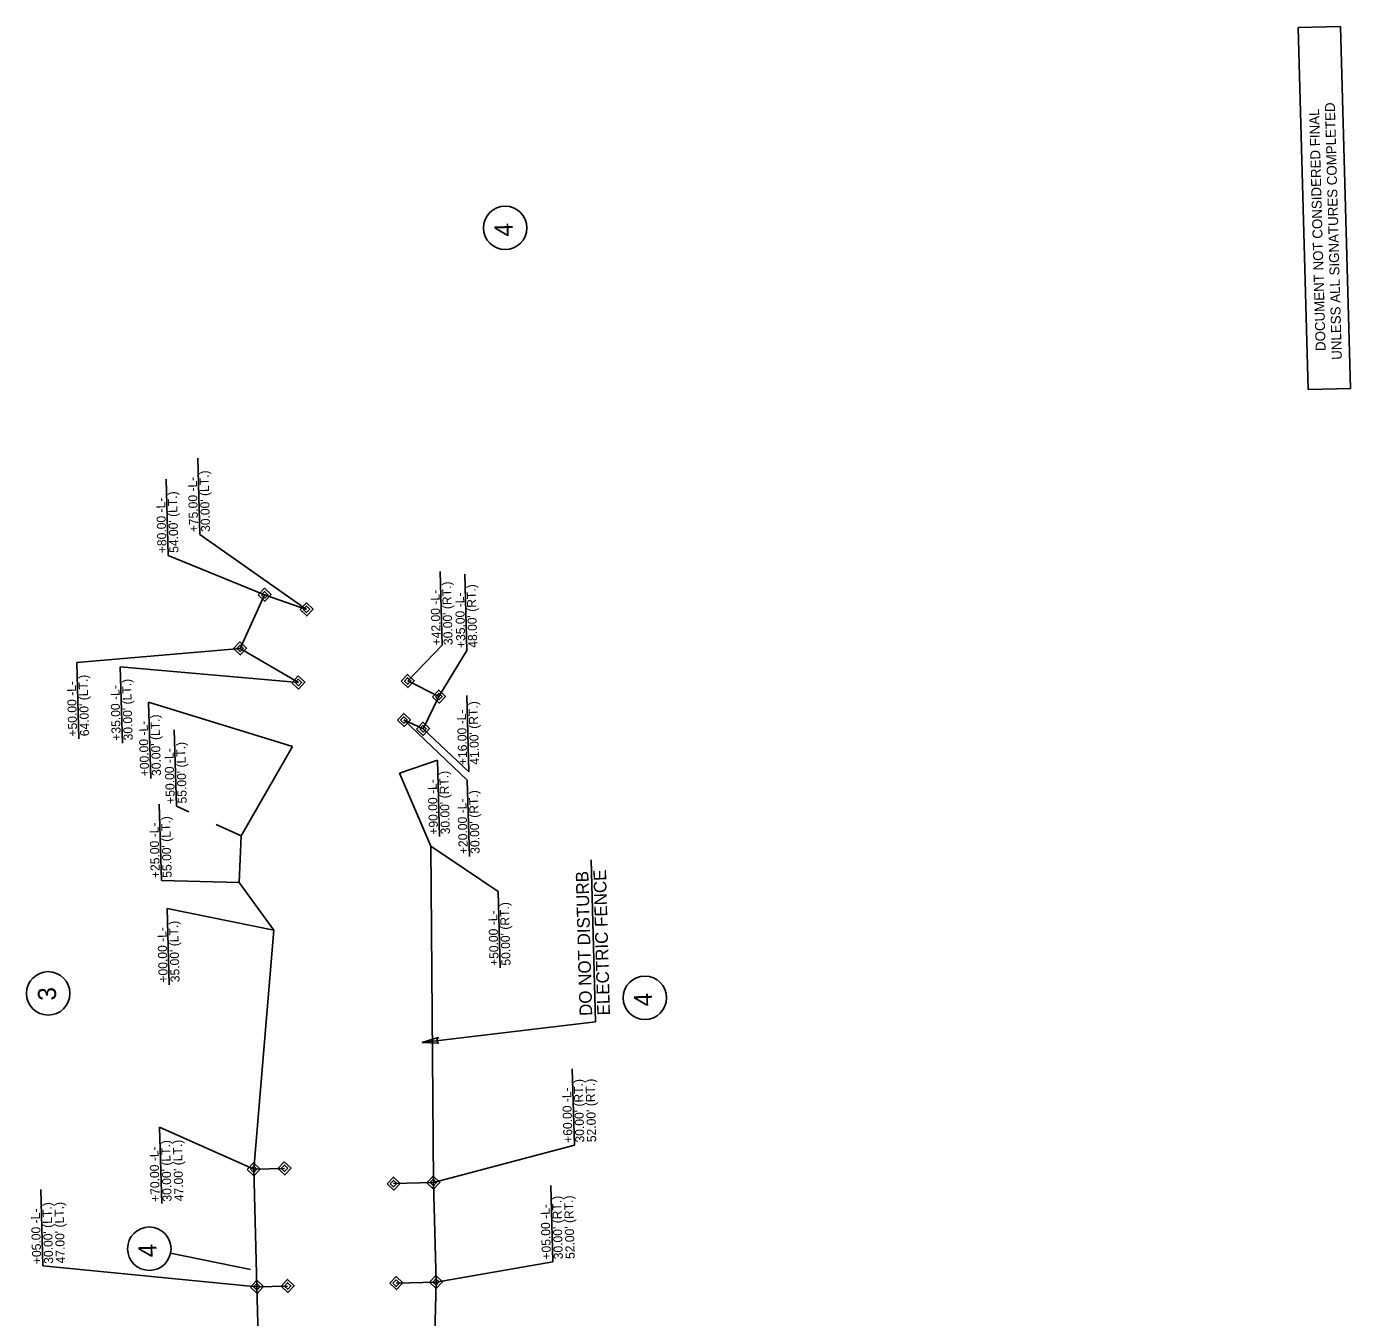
# Model space of a CAD drawing. Extents: x 1835710 to 1836442, y 994022 to 995358.
# Drawn here: x 1835710 to 1836442, y 994644 to 995358 of the extents above; entities that cross this region are included whole.
import ezdxf

# ---------------------------------------------------------------- set-up
doc = ezdxf.new("R2010")
doc.units = 0
for name, color, linetype in [('Prop Dimension', 7, 'Continuous'), ('Prop Dimension Text', 7, 'Continuous'), ('Prop Easement Construction', 7, 'Continuous'), ('Prop Easement Construction Station Offsets', 7, 'Continuous'), ('Prop Easement Permanent Drainage', 7, 'Continuous'), ('Prop Easement Permanent Drainage Station Offsets', 7, 'Continuous'), ('Prop Parcel Number CELL', 7, 'Continuous'), ('Prop ROW Marker CELL', 7, 'Continuous'), ('Prop ROW Permanent Easement CELL', 7, 'Continuous'), ('Prop ROW Station Offsets', 7, 'Continuous'), ('Prop ROW Text', 7, 'Continuous'), ('Prop Terminator CELL', 7, 'Continuous'), ('Sheet Sticker Exception Certification CELL', 7, 'Continuous')]:
    doc.layers.add(name, color=color, linetype=linetype)

msp = doc.modelspace()

# ---------------------------------------------------------------- linework, layer by layer
at = {"layer": 'Prop Dimension'}
for p in [(1836022.11, 994897.14), (1835928.86, 994796.23)]:
    msp.add_line(p, (1836024.55, 994807.69), dxfattribs=at)
at = {"layer": 'Prop Easement Construction'}
for p, q in [((1835828.79, 994910.29), (1835857.17, 994959.67)), ((1835933.64, 994904.69), (1835916.21, 994945.01)), ((1835827.6, 994884.56), (1835828.79, 994910.29)), ((1835934.97, 994718.82), (1835933.64, 994904.69)), ((1835846.75, 994858.3), (1835827.6, 994884.56)), ((1835835.74, 994726.16), (1835846.75, 994858.3)), ((1835933.19, 994523.7), (1835936.44, 994663.83)), ((1835841.09, 994526.23), (1835837.48, 994661.18))]:
    msp.add_line(p, q, dxfattribs=at)
at = {"layer": 'Prop Easement Construction Station Offsets'}
for p, q in [((1835778.8, 994941.99), (1835777.64, 994984.2)), ((1835777.64, 994984.2), (1835857.17, 994959.67)), ((1835793.01, 994926.79), (1835791.86, 994968.99)), ((1835937.25, 994952.15), (1835916.21, 994945.01)), ((1835938.4, 994909.95), (1835937.25, 994952.15)), ((1835784.72, 994885.75), (1835783.57, 994927.95)), ((1835793.01, 994926.79), (1835799.9, 994923.61)), ((1835814.99, 994916.65), (1835828.79, 994910.29)), ((1835970.74, 994879.6), (1835933.64, 994904.69)), ((1835784.72, 994885.75), (1835827.6, 994884.56)), ((1835971.9, 994837.39), (1835970.74, 994879.6)), ((1835789.1, 994828.01), (1835787.95, 994870.21)), ((1835787.95, 994870.21), (1835846.75, 994858.3))]:
    msp.add_line(p, q, dxfattribs=at)
at = {"layer": 'Prop Easement Permanent Drainage'}
for p, q in [((1835828.18, 995013.95), (1835841.73, 995043.55)), ((1835841.73, 995043.55), (1835864.91, 995035.51)), ((1835860.39, 994995.1), (1835828.18, 995013.95)), ((1835920.79, 994995.94), (1835938, 994987.29)), ((1835929.27, 994969.5), (1835938, 994987.29)), ((1835918.67, 994974.41), (1835929.27, 994969.5)), ((1835852.73, 994726.62), (1835835.74, 994726.16)), ((1835837.48, 994661.18), (1835835.74, 994726.16)), ((1835934.97, 994718.82), (1835912.98, 994718.23)), ((1835936.44, 994663.83), (1835934.97, 994718.82)), ((1835936.44, 994663.83), (1835914.45, 994663.25)), ((1835854.47, 994661.64), (1835837.48, 994661.18))]:
    msp.add_line(p, q, dxfattribs=at)
at = {"layer": 'Prop Easement Permanent Drainage Station Offsets'}
for p, q in [((1835805.91, 995076.83), (1835804.76, 995119.03)), ((1835788.44, 995065.26), (1835787.29, 995107.47)), ((1835805.91, 995076.83), (1835864.91, 995035.51)), ((1835788.44, 995065.26), (1835841.73, 995043.55)), ((1835939.91, 995015.72), (1835938.79, 995056.52)), ((1835953.54, 995012.84), (1835952.39, 995055.04)), ((1835939.91, 995015.72), (1835920.79, 994995.94)), ((1835737.96, 995006.14), (1835828.18, 995013.95)), ((1835953.54, 995012.84), (1835938, 994987.29)), ((1835739.12, 994963.94), (1835737.96, 995006.14)), ((1835763.15, 994961.64), (1835761.99, 995003.85)), ((1835761.99, 995003.85), (1835860.39, 994995.1)), ((1835954.64, 994945.75), (1835953.49, 994987.95)), ((1835953.68, 994941.21), (1835918.67, 994974.41)), ((1835954.64, 994945.75), (1835929.27, 994969.5)), ((1835954.84, 994899.01), (1835953.68, 994941.21)), ((1836012.87, 994739.44), (1836011.72, 994781.64)), ((1835784.9, 994707.28), (1835783.74, 994749.48)), ((1835783.74, 994749.48), (1835835.74, 994726.16)), ((1836012.87, 994739.44), (1835934.97, 994718.82)), ((1836000.98, 994674.91), (1835999.82, 994717.12)), ((1835719.29, 994672.75), (1835718.14, 994714.95)), ((1835719.29, 994672.75), (1835837.48, 994661.18)), ((1836000.98, 994674.91), (1835936.44, 994663.83))]:
    msp.add_line(p, q, dxfattribs=at)
at = {"layer": 'Prop Parcel Number CELL'}
for p, q in [((1835974.62, 995246.27), (1835974.62, 995246.27)), ((1835722.18, 994823.34), (1835722.18, 994823.34)), ((1836051.82, 994820.9), (1836051.82, 994820.9)), ((1835778.04, 994682.25), (1835778.04, 994682.25))]:
    msp.add_line(p, q, dxfattribs=at)
for centre in [(1835974.62, 995246.27), (1835722.18, 994823.34), (1836051.82, 994820.9), (1835778.04, 994682.25)]:
    msp.add_circle(centre, 12, dxfattribs=at)
at = {"layer": 'Prop ROW Marker CELL'}
for p, q in [((1835841.73, 995043.55), (1835841.73, 995043.55)), ((1835864.91, 995035.51), (1835864.91, 995035.51)), ((1835828.18, 995013.95), (1835828.18, 995013.95)), ((1835860.39, 994995.1), (1835860.39, 994995.1)), ((1835920.79, 994995.94), (1835920.79, 994995.94)), ((1835938, 994987.29), (1835938, 994987.29)), ((1835918.67, 994974.41), (1835918.67, 994974.41)), ((1835929.27, 994969.5), (1835929.27, 994969.5)), ((1835835.74, 994726.16), (1835835.74, 994726.16)), ((1835852.73, 994726.62), (1835852.73, 994726.62)), ((1835912.98, 994718.23), (1835912.98, 994718.23)), ((1835934.97, 994718.82), (1835934.97, 994718.82)), ((1835936.44, 994663.83), (1835936.44, 994663.83)), ((1835837.48, 994661.18), (1835837.48, 994661.18)), ((1835854.47, 994661.64), (1835854.47, 994661.64)), ((1835914.45, 994663.25), (1835914.45, 994663.25))]:
    msp.add_line(p, q, dxfattribs=at)
at = {"layer": 'Prop ROW Permanent Easement CELL'}
for points in [[(1835838.13, 995043.46), (1835841.63, 995047.15), (1835845.33, 995043.65), (1835841.83, 995039.96)], [(1835839.93, 995043.5), (1835841.68, 995045.35), (1835843.53, 995043.6), (1835841.78, 995041.75)], [(1835861.32, 995035.41), (1835864.82, 995039.11), (1835868.51, 995035.61), (1835865.01, 995031.91)], [(1835863.11, 995035.46), (1835864.86, 995037.31), (1835866.71, 995035.56), (1835864.96, 995033.71)], [(1835824.59, 995013.86), (1835828.09, 995017.55), (1835831.78, 995014.05), (1835828.28, 995010.36)], [(1835826.38, 995013.91), (1835828.14, 995015.75), (1835829.98, 995014), (1835828.23, 995012.15)], [(1835856.79, 994995), (1835860.3, 994998.7), (1835863.99, 994995.2), (1835860.49, 994991.5)], [(1835858.59, 994995.05), (1835860.34, 994996.9), (1835862.19, 994995.15), (1835860.44, 994993.3)], [(1835917.2, 994995.84), (1835920.7, 994999.54), (1835924.39, 994996.04), (1835920.89, 994992.34)], [(1835919, 994995.89), (1835920.75, 994997.74), (1835922.59, 994995.99), (1835920.84, 994994.14)], [(1835934.4, 994987.19), (1835937.9, 994990.89), (1835941.6, 994987.39), (1835938.1, 994983.69)], [(1835936.2, 994987.24), (1835937.95, 994989.09), (1835939.8, 994987.34), (1835938.05, 994985.49)], [(1835915.08, 994974.31), (1835918.58, 994978.01), (1835922.27, 994974.51), (1835918.77, 994970.81)], [(1835916.88, 994974.36), (1835918.63, 994976.21), (1835920.47, 994974.46), (1835918.72, 994972.61)], [(1835925.67, 994969.41), (1835929.17, 994973.1), (1835932.87, 994969.6), (1835929.37, 994965.9)], [(1835927.47, 994969.45), (1835929.22, 994971.3), (1835931.07, 994969.55), (1835929.32, 994967.7)], [(1835832.14, 994726.06), (1835835.64, 994729.76), (1835839.33, 994726.26), (1835835.83, 994722.56)], [(1835849.13, 994726.52), (1835852.63, 994730.22), (1835856.33, 994726.72), (1835852.83, 994723.02)], [(1835833.94, 994726.11), (1835835.69, 994727.96), (1835837.53, 994726.21), (1835835.78, 994724.36)], [(1835850.93, 994726.57), (1835852.68, 994728.42), (1835854.53, 994726.67), (1835852.78, 994724.82)], [(1835931.37, 994718.72), (1835934.87, 994722.41), (1835938.57, 994718.91), (1835935.07, 994715.22)], [(1835909.38, 994718.13), (1835912.88, 994721.83), (1835916.57, 994718.32), (1835913.07, 994714.63)], [(1835911.18, 994718.18), (1835912.93, 994720.03), (1835914.77, 994718.28), (1835913.02, 994716.43)], [(1835933.17, 994718.77), (1835934.92, 994720.61), (1835936.77, 994718.86), (1835935.02, 994717.02)], [(1835833.88, 994661.09), (1835837.38, 994664.78), (1835841.07, 994661.28), (1835837.57, 994657.59)], [(1835850.87, 994661.54), (1835854.37, 994665.24), (1835858.07, 994661.74), (1835854.57, 994658.04)], [(1835910.85, 994663.15), (1835914.35, 994666.84), (1835918.05, 994663.34), (1835914.55, 994659.65)], [(1835912.65, 994663.2), (1835914.4, 994665.05), (1835916.25, 994663.3), (1835914.5, 994661.45)], [(1835932.84, 994663.74), (1835936.34, 994667.43), (1835940.04, 994663.93), (1835936.54, 994660.24)], [(1835934.64, 994663.79), (1835936.39, 994665.63), (1835938.24, 994663.88), (1835936.49, 994662.04)], [(1835835.68, 994661.14), (1835837.43, 994662.98), (1835839.27, 994661.23), (1835837.52, 994659.39)], [(1835852.67, 994661.59), (1835854.42, 994663.44), (1835856.27, 994661.69), (1835854.52, 994659.84)]]:
    msp.add_lwpolyline(points, close=True, dxfattribs=at)
at = {"layer": 'Prop ROW Station Offsets'}
msp.add_line((1835789.8, 994679.84), (1835833.92, 994670.77), dxfattribs=at)
at = {"layer": 'Prop Terminator CELL'}
msp.add_lwpolyline([(1835937.98, 994795.77), (1835928.86, 994796.23), (1835937.65, 994798.9), (1835936.7, 994797.17)], close=True, dxfattribs=at)
at = {"layer": 'Sheet Sticker Exception Certification CELL'}
for p, q in [((1836418.15, 995156.98), (1836412.69, 995356.94)), ((1836412.7, 995356.94), (1836436.19, 995357.58)), ((1836436.18, 995357.58), (1836441.64, 995157.62)), ((1836441.64, 995157.62), (1836418.15, 995156.98))]:
    msp.add_line(p, q, dxfattribs=at)

# ---------------------------------------------------------------- texts
at = {"layer": 'Prop Dimension Text'}
for s, p in [('ELECTRIC FENCE', (1836032.54, 994811.24)), ('DO NOT DISTURB', (1836022.75, 994810.97))]:
    msp.add_text(s, height=7, rotation=91.56434, dxfattribs=at).set_placement(p)
at = {"layer": 'Prop Easement Construction Station Offsets'}
for s, p in [('+00.00 -L-', (1835777.96, 994943.35)), ("30.00' (LT.)", (1835784.51, 994943.53)), ('+50.00 -L-', (1835792.18, 994928.15)), ("55.00' (LT.)", (1835798.73, 994928.33)), ("30.00' (RT.)", (1835944.14, 994911.27)), ('+90.00 -L-', (1835937.59, 994911.09)), ("55.00' (LT.)", (1835790.44, 994887.29)), ('+25.00 -L-', (1835783.88, 994887.11)), ('+50.00 -L-', (1835971.08, 994838.54)), ("50.00' (RT.)", (1835977.63, 994838.72)), ("35.00' (LT.)", (1835794.82, 994829.55)), ('+00.00 -L-', (1835788.26, 994829.37))]:
    msp.add_text(s, height=5, rotation=91.56434, dxfattribs=at).set_placement(p)
at = {"layer": 'Prop Easement Permanent Drainage Station Offsets'}
for s, p in [("30.00' (LT.)", (1835811.63, 995078.37)), ('+75.00 -L-', (1835805.08, 995078.19)), ('+80.00 -L-', (1835787.6, 995066.62)), ("54.00' (LT.)", (1835794.16, 995066.8)), ('+42.00 -L-', (1835939.11, 995015.68)), ("30.00' (RT.)", (1835945.66, 995015.86)), ('+35.00 -L-', (1835952.71, 995014.2)), ("48.00' (RT.)", (1835959.26, 995014.37)), ('+50.00 -L-', (1835738.28, 994965.3)), ("64.00' (LT.)", (1835744.83, 994965.48)), ('+35.00 -L-', (1835762.31, 994963)), ("30.00' (LT.)", (1835768.86, 994963.18)), ('+16.00 -L-', (1835953.74, 994949.55)), ("41.00' (RT.)", (1835960.29, 994949.73)), ("30.00' (RT.)", (1835960.55, 994900.55)), ('+20.00 -L-', (1835954, 994900.37)), ("30.00' (RT.)", (1836018.4, 994740.99)), ("52.00' (RT.)", (1836024.95, 994741.17)), ('+60.00 -L-', (1836011.85, 994740.81)), ('+70.00 -L-', (1835783.85, 994708.17)), ("30.00' (LT.)", (1835790.4, 994708.35)), ("47.00' (LT.)", (1835796.95, 994708.53)), ("47.00' (LT.)", (1835731.49, 994674.16)), ("30.00' (RT.)", (1836006.51, 994676.47)), ("52.00' (RT.)", (1836013.06, 994676.65)), ('+05.00 -L-', (1835718.38, 994673.8)), ("30.00' (LT.)", (1835724.93, 994673.98)), ('+05.00 -L-', (1835999.96, 994676.29))]:
    msp.add_text(s, height=5, rotation=91.56434, dxfattribs=at).set_placement(p)
at = {"layer": 'Prop ROW Text'}
for s, p in [('4', (1835978.87, 995241.62)), ('3', (1835726.61, 994819.46)), ('4', (1836055.92, 994816.25)), ('4', (1835782.15, 994677.61))]:
    msp.add_text(s, height=10, rotation=91.56434, dxfattribs=at).set_placement(p)
at = {"layer": 'Sheet Sticker Exception Certification CELL'}
for s, p in [('UNLESS ALL SIGNATURES COMPLETED', (1836436.85, 995173.5)), ('DOCUMENT NOT CONSIDERED FINAL', (1836427.91, 995178.33))]:
    msp.add_text(s, height=5.5, rotation=91.56434, dxfattribs=at).set_placement(p)

doc.saveas('drawing.dxf')
